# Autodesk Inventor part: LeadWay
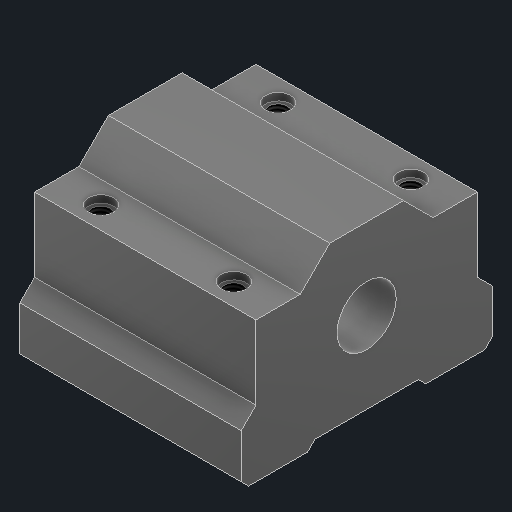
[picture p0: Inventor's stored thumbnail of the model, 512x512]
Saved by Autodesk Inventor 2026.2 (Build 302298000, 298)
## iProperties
Created: 2025-11
Part Number: LeadWay
Material: ABS 플라스틱
Document SubType Name: Modeling
Designer: work
Density: 1.06 g/cm^3
Appearance: 매끄러움 - 검은색
Author: work
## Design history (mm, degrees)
sketch "스케치1"
  geometry: L1 (0, 0)-(22, 0); L2 (0, 0)-(0, -17); L3 (0, -17)-(6, -17); L4 (6, -17)-(8, -15); L5 (8, -15)-(18, -15); L6 (18, -15)-(18, -9); L7 (18, -9)-(22, -5); L8 (22, -5)-(22, 0); L9 (18, -12)-(0, -12); L10 (0, -7)-(-1, -8); L11 (-1, -8)-(-1, -16); L12 (-1, -16)-(0, -17); L13 (-1, -12)-(0, -12); L14 (0, 7)-(-1, 8); L15 (-1, 16)-(0, 17); L16 (-1, 12)-(0, 12); L17 (0, 0)-(0, 17); L18 (6, 17)-(8, 15); L19 (8, 15)-(18, 15); L20 (18, 12)-(0, 12); L21 (18, 15)-(18, 9); L22 (18, 9)-(22, 5); L23 (0, 17)-(6, 17); L24 (-1, 8)-(-1, 16); L25 (22, 5)-(22, 0); C1 r 4 at (11, 0); 1 further point
  constraints: 50 end point, 12 symmetric about line, 4 midpoint, 4 perpendicular, 4 point on line, 3 vertical, 1 centre point, 1 horizontal, 1 parallel
  dimensions: "d0" = 22 distance of L1.start L1.end; "d1" = 6 distance of L2.end L3.end; "d2" = 8 horizontal distance of L2.end L4.end; "d3" = 18 distance between parallel lines of L2 L6; "d4" = 8 diameter of C1; "d5" = 17 distance of L1.start L2.end; "d6" = 5 distance between parallel lines of L3 L9; "d7" = 135 deg angle of L8 L7; "d8" = 135 deg angle of L3 L4; "d9" = 45 deg angle of L2 L10; "d10" = 45 deg angle of L2 L12; "d11" = 1 distance between parallel lines of L2 L11
extrude "돌출1" new body sketch "스케치1" distance "d12" = 30; taper "d13" = 0 deg
sketch "스케치2"
  geometry: L1 (0, 6)-(0, 0) reference; L2 (0, 0)-(30, 0) reference; L3 (30, 6)-(30, 0) reference; L4 (0, 6)-(30, 6) reference; L5 (0, 30)-(0, 24) reference; L6 (0, 24)-(30, 24) reference; L7 (30, 30)-(30, 24) reference; L8 (0, 30)-(30, 30) reference; L9 (0, 3)-(30, 3); L10 (0, 15)-(30, 15); 4 further points
  constraints: 4 end point, 2 midpoint, 2 point on line, 2 symmetric about line, 1 horizontal
  dimensions: "d14" = 18 distance of point (6, 3) point (24, 3); "d15" = 6 distance from line of L1 point (6, 3)
hole "구멍1" sketch "스케치2" at (6, 3), (24, 3), (6, 27), (24, 27) diameter "d16" = 2.459; stored, may be unused: countersink angle "d20" = 90 deg, drill point angle "d22" = 118 deg; dims "d17" = 6, "d18" = 3.4, "d19" = 1, "d21" = 8
node "솔리드1"
node "투영된 루프1"
node "투영된 루프2"
feature "A9D066F2-1C7D-4E18-AEED-F7BC21143FA4" dims "d16" = 2.459, "d17" = 6, "d18" = 3.4, "d19" = 1, "d20" = 90 deg, "d21" = 8, "d22" = 118 deg
